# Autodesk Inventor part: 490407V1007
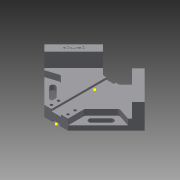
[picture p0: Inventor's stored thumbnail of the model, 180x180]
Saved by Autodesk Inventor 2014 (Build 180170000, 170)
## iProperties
Created: 2019-04
Part Number: 490407V1007
Material: Generic
Document SubType Name: Modeling
Designer: kh
Density: 1 g/cm^3
Appearance: Default
Mass: 222.769 g
Surface Area: 426.144 cm^2
Volume: 222.769 cm^3
Author: kh
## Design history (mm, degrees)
sketch "Sketch1"
  geometry: L1 (-84.853, 0)-(-35.355, 49.497); L2 (-35.355, 49.497)-(-14.005, 28.147); L3 (-14.005, 28.147)-(14.005, 28.147); L4 (14.005, 28.147)-(35.355, 49.497); L5 (35.355, 49.497)-(84.853, 0); L6 (84.853, 0)-(20, -64.853); L7 (20, -64.853)-(-20, -64.853); L8 (-20, -64.853)-(-84.853, 0); L9 (0, 130.154)-(0, -117.428); L10 (-35.355, 49.497)-(0, 84.853); L11 (35.355, 49.497)-(29.217, 55.636); L12 (29.217, 55.636)-(0, 84.853); L13 (-74.246, -10.607)-(-24.749, 38.891); L14 (24.749, 38.891)-(74.246, -10.607); 1 further point
  constraints: 28 end point, 7 perpendicular, 7 point on line, 4 parallel, 1 vertical
  dimensions: "d6" = 120 distance between parallel lines of L6 L1; "d7" = 120 distance between parallel lines of L8 L5; "d8" = 60 distance from line of point (0, 0) L5; "d9" = 60 distance from line of point (0, 0) L1; "d10" = 40 distance of L6.end L7.end; "d11" = 20 distance from line of L9 L7.end; "d12" = 50 distance from line of L10.end L2; "d13" = 50 distance of L4.end L10.end; "d14" = 93 distance between parallel lines of L7 L3; "d15" = 15 distance between parallel lines of L14 L5; "d16" = 15 distance between parallel lines of L13 L1
extrude "Extrusion1" new body sketch "Sketch1" distance "d17" = 42; taper "d18" = 0 deg
extrude "Extrusion2" join sketch "Sketch1" distance "d19" = 18; taper "d20" = 0 deg
sketch "Sketch2"
  geometry: 1 further point
sketch "Sketch3"
  geometry: L1 (-24.749, 38.891)-(-74.246, -10.607) reference; L2 (-20, -64.853)-(-74.246, -10.607) reference; L3 (20, -64.853)-(-20, -64.853) reference; L4 (74.246, -10.607)-(20, -64.853) reference; L5 (84.853, 0)-(74.246, -10.607) reference; L6 (35.355, 49.497)-(84.853, 0) reference; L7 (24.749, 38.891)-(35.355, 49.497) reference; L8 (74.246, -10.607)-(24.749, 38.891) reference; L9 (-24.749, 38.891)-(-14.005, 28.147) reference; L10 (-35.355, 49.497)-(-24.749, 38.891) reference; L11 (-84.853, 0)-(-35.355, 49.497) reference; L12 (-74.246, -10.607)-(-84.853, 0) reference; L13 (14.005, 28.147)-(24.749, 38.891) reference; L14 (-14.005, 28.147)-(14.005, 28.147) reference; L15 (-70.711, -14.142)-(-49.497, -7.071); L16 (-49.497, -7.071)-(-20, -36.569); L17 (-20, -36.569)-(-20, -64.853); L18 (-49.497, -21.213)-(-32.527, -38.184); L19 (-52.679, -24.395)-(-35.709, -41.366); L20 (-29.345, -35.002)-(-46.315, -18.031); L21 (0, 0)-(0, -64.853); A1 r 4.5 centre (-49.497, -21.213) between (-46.315, -18.031) and (-52.679, -24.395); A2 r 4.5 centre (-32.527, -38.184) between (-35.709, -41.366) and (-29.345, -35.002); 1 further point
  constraints: 16 end point, 4 point on circle, 4 tangent, 3 parallel, 2 centre point, 2 midpoint, 1 perpendicular, 1 point on line
  dimensions: "d21" = 20 distance of L11.start L15.start; "d22" = 20 distance between parallel lines of L16 L2; "d23" = 24 distance of L18.end L18.start; "d24" = 40 distance from line of L11 L18.start; "d25" = 30 distance from line of L11 L15.end; "d26" = 4.5 radius of A2; "d27" = 10 distance from line of L12 point (-41.012, -29.698)
  node "Project Cut Edges1"
extrude "Extrusion3" cut sketch "Sketch3" distance "d28" = 10; taper "d29" = 0 deg
extrude "Extrusion4" cut sketch "Sketch3" stored distance "d30" = 10; taper "d31" = 0 deg
mirror "Mirror1"
sketch "Sketch4"
  geometry: L1 (28, 18)-(12, 18); L2 (12, 18)-(12, 14.5); L3 (12, 14.5)-(28, 14.5); L4 (28, 14.5)-(28, 18); L5 (26, 0)-(14, 0); L6 (14, 0)-(14, 3); L7 (14, 3)-(26, 3); L8 (26, 3)-(26, 0); L9 (0, 0)-(40, 0) reference; L10 (0, 18)-(40, 18) reference; 3 further points
  constraints: 16 end point, 4 midpoint, 4 parallel, 2 horizontal, 2 perpendicular
  dimensions: "d32" = 6 distance from line of L6 point (20, 0); "d33" = 12 distance of L5.start L5.end; "d34" = 3 distance of L7.end L5.start; "d35" = 16 distance of L2.end L3.end; "d37" = 3.5 distance of L3.end L1.start
extrude "Extrusion5" cut sketch "Sketch4" stored distance "d38" = 10; taper "d39" = 0 deg
extrude "Extrusion6" cut sketch "Sketch4" stored distance "d40" = 10; taper "d41" = 0 deg
sketch "Sketch6"
  geometry: L1 (20, -64.853)-(6, -64.853) reference; L2 (6, -64.853)-(6, 28.147) reference; L3 (6, 28.147)-(14.005, 28.147) reference; L4 (14.005, 28.147)-(35.355, 49.497) reference; L5 (35.355, 49.497)-(84.853, 0) reference; L6 (84.853, 0)-(20, -64.853) reference; L7 (-29.345, -35.002)-(-46.315, -18.031) reference; L8 (-52.679, -24.395)-(-35.709, -41.366) reference; L9 (46.315, -18.031)-(29.345, -35.002) reference; L10 (35.709, -41.366)-(52.679, -24.395) reference; L11 (-84.853, 0)-(-35.355, 49.497) reference; L12 (-35.355, 49.497)-(-14.005, 28.147) reference; L13 (-14.005, 28.147)-(-6, 28.147) reference; L14 (-6, 28.147)-(-6, -64.853) reference; L15 (-6, -64.853)-(-20, -64.853) reference; L16 (-20, -64.853)-(-84.853, 0) reference; A1 r 4.5 centre (-32.527, -38.184) between (-35.709, -41.366) and (-29.345, -35.002) reference; A2 r 4.5 centre (-49.497, -21.213) between (-46.315, -18.031) and (-52.679, -24.395) reference; A3 r 4.5 centre (49.497, -21.213) between (52.679, -24.395) and (46.315, -18.031) reference; A4 r 4.5 centre (32.527, -38.184) between (29.345, -35.002) and (35.709, -41.366) reference; 5 further points
  dimensions: "d42" = 14 horizontal distance of point (0, 0) point (-14, -58.853); "d43" = 28 distance of point (14, -58.853) point (-14, -58.853); "d44" = 14 horizontal distance of point (0, 0) point (-14, -46.853); "d45" = 28 distance of point (14, -46.853) point (-14, -46.853); "d46" = 6 distance from line of L1 point (14, -58.853); "d47" = 6 distance from line of L15 point (-14, -58.853); "d48" = 12 distance of point (-14, -58.853) point (-14, -46.853); "d49" = 12 distance of point (14, -58.853) point (14, -46.853)
hole "Hole1" sketch "Sketch6" at (14, -58.853), (14, -46.853), (-14, -46.853), (-14, -58.853) diameter "d50" = 4.5; stored, may be unused: countersink angle "d54" = 90 deg, drill point angle "d56" = 118 deg; dims "d51" = 6, "d52" = 8, "d53" = 10, "d55" = 8
fillet "Fillet1" dims "d57" = 5
fillet "Fillet2" dims "d58" = 5
sketch "Sketch7"
  geometry: L1 (-15.177, 73.236)-(-108.591, -20.178); L2 (-108.591, -20.178)-(-94.425, -34.345); L3 (-94.425, -34.345)-(-1.011, 59.069); L4 (-1.011, 59.069)-(-15.177, 73.236); L5 (-35.355, 49.497)-(-24.749, 38.891) reference; L6 (-24.749, 38.891)-(-74.246, -10.607) reference; L7 (-74.246, -10.607)-(-84.853, 0) reference; L8 (-84.853, 0)-(-35.355, 49.497) reference; L9 (35.355, 49.497)-(84.853, 0) reference; L10 (84.853, 0)-(74.246, -10.607) reference; L11 (74.246, -10.607)-(24.749, 38.891) reference; L12 (24.749, 38.891)-(35.355, 49.497) reference; L13 (-1.011, 59.069)-(-108.591, -20.178); 2 further points
  constraints: 2 end point, 1 midpoint, 2 other
  dimensions: "d59" = 35 distance from line of point (-54.801, 19.445) L5; "d60" = 7.5 distance from line of L8 point (-54.801, 19.445)
emboss "Emboss1" sketch "Sketch7" dims "d6" = 120, "d7" = 120, "d8" = 60, "d9" = 60, "d10" = 40, "d11" = 20, "d12" = 50, "d13" = 50, "d14" = 93, "d15" = 15, "d16" = 15, "d61" = 0.5, "d62" = 0
sketch "Sketch8"
  geometry: 1 further point
body "Solid1"
node "Project Cut Edges2"
node "Project Cut Edges3"
